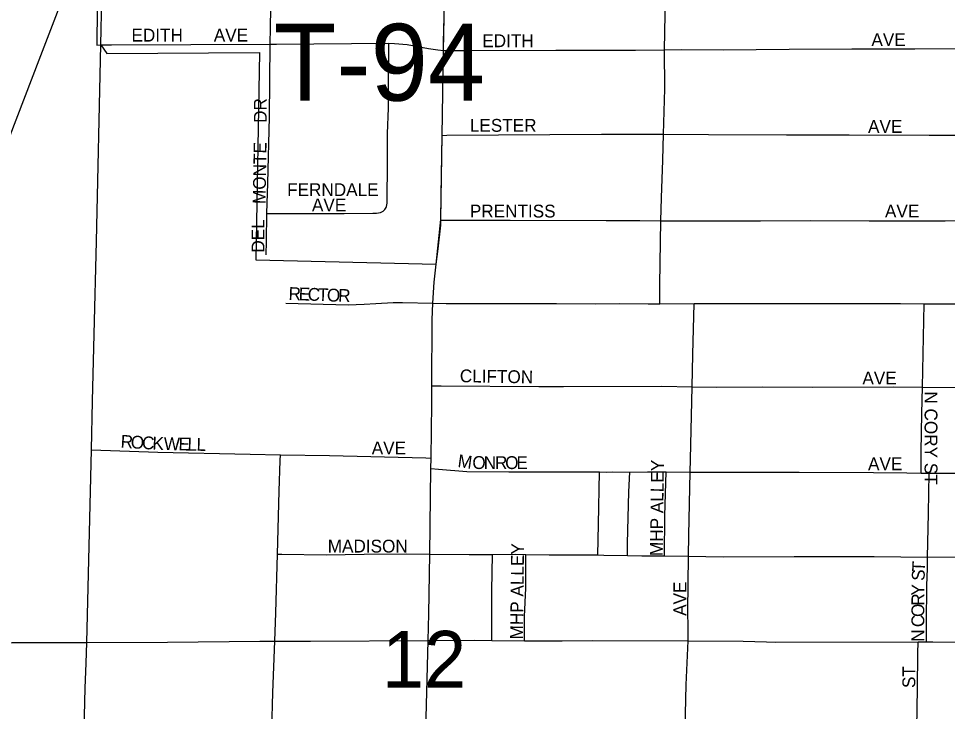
# Model space of a CAD drawing. Extents: x 1587405 to 1714697, y 1028970 to 1155083.
# Drawn here: x 1646970 to 1650593, y 1116017 to 1118719 of the extents above; entities that cross this region are included whole.
import ezdxf

# ---------------------------------------------------------------- set-up
doc = ezdxf.new("R2010")
doc.units = 0
for name, color, linetype in [('GM_X_City_Street', 7, 'Continuous'), ('GM_X_City_Street_Text', 7, 'Continuous'), ('GM_X_Corporation', 7, 'Continuous'), ('GM_X_Interstate_Route', 7, 'Continuous'), ('GM_X_Section_Text', 7, 'Continuous'), ('GM_X_Township_Road_Text', 7, 'Continuous'), ('GM_X_Township_Subdivision', 7, 'Continuous'), ('GM_X_Township_Subdivision_Text', 7, 'Continuous'), ('GM_X_US_Route', 7, 'Continuous')]:
    doc.layers.add(name, color=color, linetype=linetype)

msp = doc.modelspace()

# ---------------------------------------------------------------- linework, layer by layer
at = {"layer": 'GM_X_City_Street'}
for points in [[(1649489.9, 1118597.5), (1649493.6, 1118805), (1649492.9, 1118886.9), (1649492.1, 1118924.4)], [(1647290.5, 1118616.8), (1647294.5, 1118800.9), (1647298, 1118866.1), (1647302.1, 1118898.3), (1647306.2, 1118918.2)], [(1648627.1, 1118595.4), (1648627.6, 1118627.5), (1648633.7, 1118874), (1648633.6, 1118919.4)], [(1647254.2, 1117037.7), (1647258.5, 1117226.6), (1647265.2, 1117488.9), (1647273.7, 1117849.8), (1647290.5, 1118616.8)], [(1648622.4, 1118263.8), (1648627.1, 1118595.4)], [(1648627.1, 1118595.4), (1648705, 1118595.3), (1649065.2, 1118596.5), (1649376.3, 1118596.2), (1649489.9, 1118597.5)], [(1649486, 1118268.6), (1649490.5, 1118445.5), (1649489.9, 1118597.5)], [(1649489.9, 1118597.5), (1649555.7, 1118598.3), (1649719.1, 1118597.3), (1649975.7, 1118599.9), (1650220.7, 1118601.6), (1650466.4, 1118601.8), (1650645, 1118602.8), (1650781.5, 1118602.7), (1651037.8, 1118603.5), (1651121.4, 1118603.5), (1651216.1, 1118602.8), (1651273.4, 1118602.9)], [(1648622.4, 1118263.8), (1648640, 1118264), (1649244.1, 1118268.5), (1649486, 1118268.6)], [(1649475.9, 1117931), (1649477.6, 1118019.9), (1649482.9, 1118167), (1649486, 1118268.6)], [(1649486, 1118268.6), (1649661.7, 1118266.6), (1649964.9, 1118265.6), (1650209.9, 1118265.4), (1650522, 1118264.1), (1650725, 1118264.2), (1650817.4, 1118263.6)], [(1648617.3, 1117932.8), (1648619, 1118030), (1648622.4, 1118263.8)], [(1648599, 1117761), (1648606.1, 1117820.8), (1648616.7, 1117913.5), (1648617.3, 1117932.8)], [(1648617.3, 1117932.8), (1648644.4, 1117932.7), (1648887.7, 1117932.9), (1649262.3, 1117932.1), (1649393.1, 1117932), (1649475.9, 1117931)], [(1649471, 1117607), (1649471.3, 1117682.4), (1649475.9, 1117931)], [(1649475.9, 1117931), (1649554.6, 1117930.9), (1649864.4, 1117930.6), (1650059.7, 1117931.4), (1650288.5, 1117930.6), (1650583.9, 1117930.1), (1650810.2, 1117931.7)], [(1648585.5, 1117609), (1648590.8, 1117691.5), (1648599, 1117761)], [(1648012.3, 1117609.3), (1648256, 1117603), (1648317.5, 1117605), (1648363.7, 1117608.2), (1648431.6, 1117611.4), (1648467.6, 1117612.1), (1648585.5, 1117609)], [(1648581.8, 1117287.2), (1648582.9, 1117544.8), (1648585.5, 1117609)], [(1648585.5, 1117609), (1648637.8, 1117608), (1649068, 1117607.4), (1649219, 1117607), (1649313.5, 1117607.5), (1649425.6, 1117606.8), (1649471, 1117607)], [(1649471, 1117607), (1649604.9, 1117607.5)], [(1649597, 1117283.2), (1649599.9, 1117409.6), (1649604.9, 1117607.5)], [(1649604.9, 1117607.5), (1649651.7, 1117607.7), (1649797.8, 1117608), (1650041, 1117608.1), (1650410.3, 1117608.3), (1650502.8, 1117606.8)], [(1650495.8, 1117281.3), (1650502.8, 1117606.8)], [(1650502.8, 1117606.8), (1650652.4, 1117607.2), (1650805.3, 1117607.7)], [(1648578.8, 1117005.2), (1648581.6, 1117217.8), (1648581.8, 1117287.2)], [(1648581.8, 1117287.2), (1648618.1, 1117287), (1648998.8, 1117284.5), (1649096, 1117284), (1649479.4, 1117285), (1649597, 1117283.2)], [(1649589.6, 1116950.4), (1649590.7, 1117000.3), (1649597, 1117283.2)], [(1649597, 1117283.2), (1649692.5, 1117281.7), (1649873.1, 1117283), (1650066.2, 1117282), (1650381.5, 1117282.5), (1650495.8, 1117281.3)], [(1650490.5, 1116946.8), (1650491.1, 1117029.3), (1650493.9, 1117179.5), (1650495.8, 1117281.3)], [(1650495.8, 1117281.3), (1650624.1, 1117279.9), (1650730.5, 1117280.3), (1650848.9, 1117276.9), (1651070.7, 1117276.6), (1651203.4, 1117276.8), (1651248.7, 1117276.9)], [(1647235.7, 1116286.3), (1647254.2, 1117037.7)], [(1647254.2, 1117037.7), (1647513.7, 1117028.5), (1647872.8, 1117020.3), (1647991.5, 1117018.3)], [(1647979.6, 1116630.3), (1647986.4, 1116875.5), (1647990.7, 1116995.4), (1647991.5, 1117018.3)], [(1647991.5, 1117018.3), (1648182.9, 1117015.4), (1648558.3, 1117005.8), (1648578.8, 1117005.2)], [(1648578.2, 1116964.9), (1648578.8, 1117005.2)], [(1648573.8, 1116630.8), (1648578.2, 1116964.9)], [(1648578.2, 1116964.9), (1648608.1, 1116962.4), (1648719.1, 1116952.9), (1648882.2, 1116951.4), (1649027, 1116951.6), (1649146.5, 1116950.8), (1649235.7, 1116950.9)], [(1649229.3, 1116627.1), (1649231.8, 1116746), (1649235.7, 1116950.9)], [(1649235.7, 1116950.9), (1649262.5, 1116950.1), (1649288.3, 1116950.9), (1649354.4, 1116950.1)], [(1649344.7, 1116625.4), (1649344.8, 1116672.2), (1649350.5, 1116872.9), (1649354.4, 1116950.1)], [(1649354.4, 1116950.1), (1649423.7, 1116950.9), (1649478.4, 1116950.9), (1649496.3, 1116950.9)], [(1649489.7, 1116623.2), (1649490.4, 1116780.1), (1649496.3, 1116950.9)], [(1649496.3, 1116950.9), (1649589.6, 1116950.4)], [(1649583.3, 1116622), (1649584.2, 1116704.4), (1649589.6, 1116950.4)], [(1649589.6, 1116950.4), (1649674.2, 1116950), (1649966.4, 1116950), (1650015.2, 1116949.7), (1650304.3, 1116948.2), (1650435.2, 1116946.9), (1650490.5, 1116946.8)], [(1650490.5, 1116946.8), (1650521.6, 1116946.8)], [(1650515.7, 1116618.4), (1650516.6, 1116674.4), (1650519.1, 1116790.4), (1650521.6, 1116946.8)], [(1650521.6, 1116946.8), (1650680.7, 1116946.7), (1650825, 1116948), (1650889.2, 1116947.4), (1651100.9, 1116947.5), (1651208.3, 1116947.8), (1651242.4, 1116947.9)], [(1647969.1, 1116290.7), (1647973.3, 1116401), (1647979.6, 1116630.3)], [(1647979.6, 1116630.3), (1647996.7, 1116630.1), (1648170.2, 1116628.2), (1648318.1, 1116630.3), (1648482.4, 1116631.8), (1648573.8, 1116630.8)], [(1648568.1, 1116293.4), (1648570.9, 1116398), (1648573.8, 1116630.8)], [(1648573.8, 1116630.8), (1648728.2, 1116629.1), (1648819.3, 1116629.4)], [(1648816, 1116293.9), (1648815.7, 1116342.2), (1648815.5, 1116374.4), (1648816.6, 1116487.2), (1648819.3, 1116629.4)], [(1648819.3, 1116629.4), (1648908.9, 1116629.7), (1648948.9, 1116629.2)], [(1648943.2, 1116292.6), (1648943.5, 1116320.9), (1648944.1, 1116386.7), (1648948.4, 1116497.9), (1648949.3, 1116595.3), (1648948.9, 1116629.2)], [(1648948.9, 1116629.2), (1649040.2, 1116628.1), (1649229.3, 1116627.1)], [(1649229.3, 1116627.1), (1649253.6, 1116627), (1649344.7, 1116625.4)], [(1649344.7, 1116625.4), (1649401.6, 1116624.3), (1649489.7, 1116623.2)], [(1649489.7, 1116623.2), (1649583.3, 1116622)], [(1649582, 1116292.2), (1649581.6, 1116342.3), (1649581.1, 1116408.3), (1649583.3, 1116622)], [(1649583.3, 1116622), (1649718.6, 1116620.4), (1649994.9, 1116620.9), (1650307, 1116620.9), (1650515.7, 1116618.4)], [(1650512, 1116288), (1650512.1, 1116315.3), (1650512.2, 1116359.2), (1650512.9, 1116508.6), (1650515, 1116574.9), (1650515.7, 1116618.4)], [(1650515.7, 1116618.4), (1650668.5, 1116619.3), (1650848.8, 1116617.2), (1651193.6, 1116617.6), (1651235.9, 1116617.6)], [(1647225.3, 1115944.5), (1647230.2, 1116107.1), (1647233.2, 1116204.5), (1647235.7, 1116286.3)], [(1647957.5, 1115944.4), (1647961.4, 1116091.1), (1647969.1, 1116290.7)], [(1648558.8, 1115941.9), (1648568.1, 1116293.4)], [(1649569.8, 1115950.7), (1649573.8, 1116121.1), (1649582, 1116292.2)], [(1650473.4, 1115950.9), (1650476.4, 1116106.1), (1650478.4, 1116242.6), (1650479.1, 1116287.9)]]:
    msp.add_lwpolyline(points, dxfattribs=at)
at = {"layer": 'GM_X_Corporation'}
msp.add_lwpolyline([(1647278.1, 1118901.8), (1647275.5, 1118615.8), (1647290.5, 1118616.8), (1647314.7, 1118583.4), (1647910.3, 1118587.1), (1647895.4, 1117778.2), (1648599, 1117761), (1648617.3, 1117935.4), (1648622.4, 1118263.8), (1648627.2, 1118595.4), (1648633.6, 1118919.4)], dxfattribs=at)
at = {"layer": 'GM_X_Interstate_Route'}
msp.add_lwpolyline([(1646348.2, 1116745.6), (1646365.5, 1116787.1), (1646409, 1116893.7), (1646450.2, 1116998.3), (1646702.5, 1117649.7), (1646803.8, 1117917), (1647056.7, 1118575.8), (1647183.9, 1118907.8)], dxfattribs=at)
at = {"layer": 'GM_X_Township_Subdivision'}
for points in [[(1647951.8, 1118619.6), (1647952.7, 1118684.9), (1647955.4, 1118832.9), (1647956.8, 1118882.3), (1647957.9, 1118917.8)], [(1647290.5, 1118616.8), (1647333, 1118616.9), (1647951.8, 1118619.6)], [(1647938.8, 1117959.5), (1647941.7, 1118077.1), (1647948.3, 1118335.5), (1647951.8, 1118619.6)], [(1647951.8, 1118619.6), (1647975.5, 1118619.7), (1648414, 1118623.5)], [(1648398.2, 1117975.1), (1648404.1, 1117983.1), (1648405.5, 1117986.6), (1648407.4, 1117999.3), (1648407.8, 1118005.4), (1648408.2, 1118051), (1648408.5, 1118112.4), (1648409.4, 1118179.3), (1648409.3, 1118271.1), (1648412.6, 1118370.4), (1648413.5, 1118462), (1648414, 1118623.5)], [(1648414, 1118623.5), (1648435.8, 1118622.6), (1648485.3, 1118618.1), (1648534, 1118609.5), (1648569.3, 1118603.2), (1648605.4, 1118598), (1648627.1, 1118595.4)], [(1647936.4, 1117797.7), (1647937.2, 1117849.8), (1647938.8, 1117959.5)], [(1647938.8, 1117959.5), (1648019.4, 1117958.6), (1648140.3, 1117958.7), (1648239.6, 1117958.9), (1648351.3, 1117960.4), (1648366.5, 1117960.2), (1648381.7, 1117962.8), (1648391.6, 1117968.8), (1648398.2, 1117975.1)]]:
    msp.add_lwpolyline(points, dxfattribs=at)
at = {"layer": 'GM_X_US_Route'}
for points in [[(1646823.9, 1116283.9), (1646944.8, 1116285.4), (1647235.7, 1116286.3)], [(1647235.7, 1116286.3), (1647551.4, 1116286.8), (1647911.6, 1116290.5), (1647969.1, 1116290.7), (1648108.1, 1116290.8), (1648568.1, 1116293.4), (1648746.8, 1116294.6), (1648816, 1116293.9), (1648943.2, 1116292.6), (1648992.4, 1116292.1), (1649090.6, 1116292.6), (1649207.6, 1116293.5), (1649582, 1116292.2), (1649796, 1116291.3), (1649888, 1116288.5)], [(1649888, 1116288.5), (1649923.5, 1116287.4), (1650479.1, 1116287.9), (1650512, 1116288), (1650536.4, 1116288), (1650815.5, 1116285), (1650881.3, 1116286.4), (1651228.4, 1116283.4)]]:
    msp.add_lwpolyline(points, dxfattribs=at)

# ---------------------------------------------------------------- texts
at = {"layer": 'GM_X_City_Street_Text'}
for s, rotation, p in [('EDITH', 0, (1648778.8, 1118607.9)), ('AVE', 0, (1650296.8, 1118612.3)), ('LESTER', 0, (1648730.4, 1118277.9)), ('AVE', 0, (1650283.6, 1118273.5)), ('PRENTISS', 0, (1648730.4, 1117943.5)), ('AVE', 0, (1650349.6, 1117943.5)), ('R', 357.8627, (1648022.4, 1117622.3)), ('E', 357.8415, (1648061.9, 1117620.8)), ('C', 357.8548, (1648097.1, 1117619.5)), ('T', 357.8415, (1648136.7, 1117618)), ('O', 357.8535, (1648171.9, 1117616.6)), ('R', 358.0221, (1648216, 1117615)), ('CLIFTON', 359.0295, (1648690.9, 1117301.1)), ('AVE', 0, (1650261.6, 1117292.3)), ('N CORY ST', 270, (1650504.2, 1117265.3)), ('R', 356.5494, (1647367, 1117045.9)), ('O', 356.545, (1647406.5, 1117043.5)), ('C', 356.5252, (1647450.4, 1117040.8)), ('K', 357.6848, (1647491, 1117038.4)), ('W', 358.6939, (1647536, 1117036.6)), ('E', 358.7265, (1647593.2, 1117035.3)), ('L', 358.7514, (1647628.4, 1117034.5)), ('L', 358.7434, (1647663.6, 1117033.7)), ('AVE', 0, (1648347.6, 1117019.5)), ('M', 352.0322, (1648680.7, 1116970.7)), ('O', 359.2945, (1648739.8, 1116962.8)), ('N', 359.9929, (1648784.5, 1116962.3)), ('R', 359.9941, (1648828.5, 1116962.3)), ('O', 359.9929, (1648868.1, 1116962.3)), ('E', 359.9956, (1648912.1, 1116962.3)), ('AVE', 0, (1650283.6, 1116957.9)), ('MHP ALLEY', 89.2825, (1649482.8, 1116622.7)), ('MADISON', 0, (1648176, 1116636.7)), ('MHP ALLEY', 89.2836, (1648937.2, 1116297.4)), ('T', 87.5128, (1650505.2, 1116560.6)), ('S', 87.622, (1650503.8, 1116525.5)), ('AVE', 90, (1649574.6, 1116389.7)), ('Y', 89.5191, (1650503, 1116468.7)), ('R', 89.9757, (1650503, 1116429.2)), ('O', 89.9812, (1650503, 1116385.2)), ('C', 89.9703, (1650503, 1116345.6)), ('N', 89.9781, (1650503, 1116288.5)), ('ST', 90, (1650467.8, 1116108.1))]:
    msp.add_text(s, height=50, rotation=rotation, dxfattribs=at).set_placement(p)
at = {"layer": 'GM_X_Section_Text'}
msp.add_text('12', height=221, rotation=0, dxfattribs=at).set_placement((1648387.2, 1116110))
at = {"layer": 'GM_X_Township_Road_Text'}
msp.add_text('T-94', height=300, rotation=0, dxfattribs=at).set_placement((1647964.8, 1118399))
at = {"layer": 'GM_X_Township_Subdivision_Text'}
for s, rotation, p in [('EDITH', 0, (1647410.4, 1118629.8)), ('AVE', 0, (1647731.6, 1118629.9)), ('DR', 90, (1647937.8, 1118312.5)), ('MONTE', 89.0295, (1647933.4, 1117995.8)), ('FERNDALE', 0, (1648017.6, 1118027.1)), ('AVE', 0, (1648114.4, 1117967.5)), ('DEL', 90, (1647929, 1117806.5))]:
    msp.add_text(s, height=50, rotation=rotation, dxfattribs=at).set_placement(p)

doc.saveas('drawing.dxf')
